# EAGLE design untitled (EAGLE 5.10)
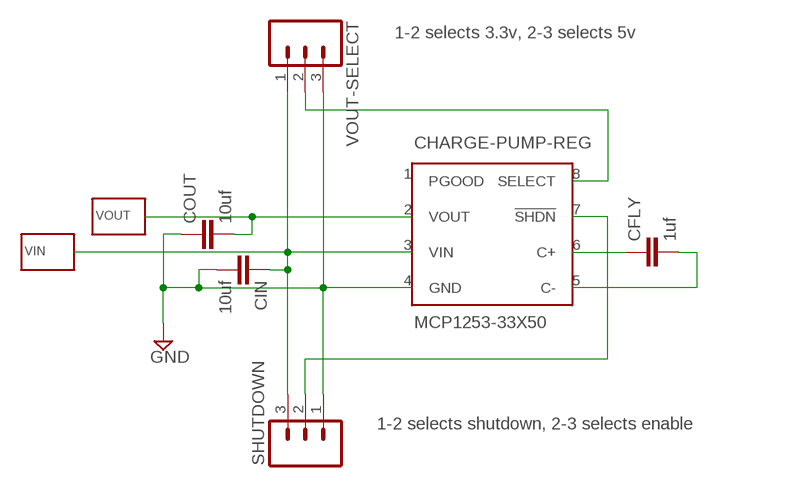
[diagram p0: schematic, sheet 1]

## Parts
CFLY  1uf  C-EUC1206  [C1206]
CHARGE-PUMP-REG  MCP1253-33X50  [8MSOP]
CIN  10uf  C-EUC1206  [C1206]
COUT  10uf  C-EUC1206  [C1206]
SHUTDOWN  M03PTH  [1X03]
VIN  WIREPAD-SMD-NO-VALUE  [WIREPAD-SMD]
VOUT  WIREPAD-SMD-NO-VALUE  [WIREPAD-SMD]
VOUT-SELECT  M03PTH  [1X03]

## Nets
GND: CHARGE-PUMP-REG.4(GND) CIN.2 COUT.1 SHUTDOWN.1 VOUT-SELECT.3
N$2: CHARGE-PUMP-REG.3(VIN) CIN.1 SHUTDOWN.3 VIN.1(P) VOUT-SELECT.1
N$3: CHARGE-PUMP-REG.2(VOUT) COUT.2 VOUT.1(P)
N$4: CHARGE-PUMP-REG.8(SELECT) VOUT-SELECT.2
N$5: CHARGE-PUMP-REG.7(!SHDN) SHUTDOWN.2
N$6: CFLY.1 CHARGE-PUMP-REG.6(C+)
N$7: CFLY.2 CHARGE-PUMP-REG.5(C-)
Unconnected: CHARGE-PUMP-REG.1(PGOOD)

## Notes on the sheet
- 1-2 selects 3.3v, 2-3 selects 5v
- 1-2 selects shutdown, 2-3 selects enable

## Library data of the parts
CFLY CIN COUT = resistor:C-EU: CAPACITOR, European symbol
CHARGE-PUMP-REG = trl:MCP1253-33X50
SHUTDOWN VOUT-SELECT = SparkFun:M03: Header 3 Standard 3-pin 0.1" header. Use with straight break away headers (SKU : PRT-00116), right angle break away headers (PRT-00553), swiss pins (PRT-00743), machine pins (PRT-00117), and female headers (PRT-00115). Molex polarized connector foot print use with SKU : PRT-08232 with associated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
VIN VOUT = trl:WIREPAD-SMD-NO-VALUE

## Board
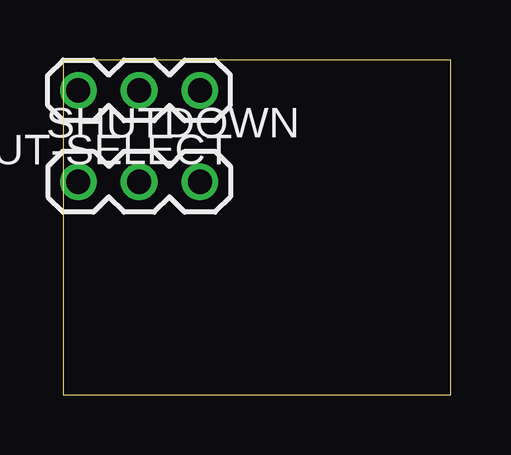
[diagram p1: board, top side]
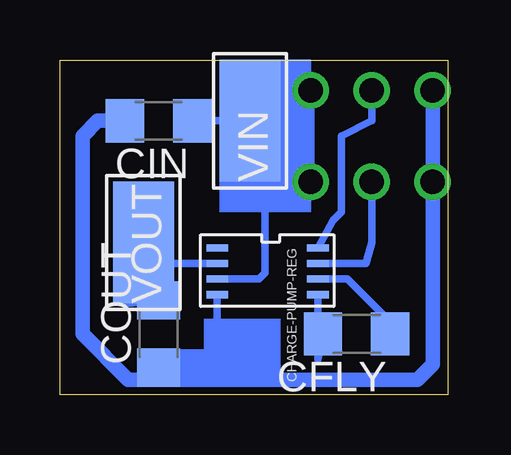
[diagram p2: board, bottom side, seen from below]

Size 16.18 x 13.96 mm. Coordinates in mm from the lower left corner, seen from the top.
Outline: 0,0 16.18,0 16.18,13.96 0,13.96 0,0
Copper layers (1*16): Top 0.035mm / dielectric 1.5mm / Bottom 0.035mm
Design rules "default": minimum track width 10mil, minimum drill 24mil, track to track 8mil, track to pad 8mil, pad to pad 8mil, via to via 8mil, smd to smd 8mil, copper to edge 40mil, drill to drill 8mil, minimum pad ring 10mil, minimum via ring 8mil, stop-mask expansion 4mil, vias tented up to drill 0mil, thermal gap 10mil

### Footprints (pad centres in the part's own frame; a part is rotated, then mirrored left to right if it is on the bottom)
C1206 = smd 1.6 x 1.8: 1 -1.4,0; 2 1.4,0
8MSOP = smd 0.3 x 0.9: 1 -1.05,-2; 2 -0.4,-2; 3 0.25,-2; 4 0.9,-2; 5 0.9,2.2; 6 0.25,2.2; 7 -0.4,2.2; 8 -1.05,2.2
1X03 = drill 1.016 round: 1 0,0; 2 2.54,0; 3 5.08,0
WIREPAD-SMD = smd 2.54 x 5.08: 1 0,0

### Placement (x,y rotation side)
CFLY  3.81,2.54 180 bottom
CHARGE-PUMP-REG  7.62,5.08 270 bottom
CIN  12.06,11.43 180 bottom
COUT  12.06,2.54 90 bottom
SHUTDOWN  0.64,8.89 0 top
VIN  8.26,11.43 0 bottom
VOUT  12.7,6.35 0 bottom
VOUT-SELECT  5.71,12.7 180 top

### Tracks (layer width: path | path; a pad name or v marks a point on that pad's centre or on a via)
GND
  Bottom 0.305: CHARGE-PUMP-REG.4 9.62,0.54 12.06,0.64 11.94,1.27 COUT.1
  Bottom 0.61: CIN.2 14.61,11.43 15.24,10.79 15.24,3.17 15.24,2.54 13.34,0.64 12.06,0.64 | 12.06,0.64 12.2,1.27 COUT.1 | VOUT-SELECT.3 SHUTDOWN.1 0.64,1.27 1.27,0.64 11.43,0.64 12.06,0.64
N$2
  Bottom 0.305: VIN.1 CIN.1 | CHARGE-PUMP-REG.3 7.87,4.83 7.62,5.08 7.62,7.62 7.62,10.16 VIN.1 | SHUTDOWN.3 VOUT-SELECT.1 6.99,12.7 VIN.1
N$3
  Bottom 0.305: CHARGE-PUMP-REG.2 13.34,5.48 | 13.34,5.48 COUT.2 | COUT.2 13.34,3.81 COUT.2 | COUT.2 13.34,5.48 | 13.34,5.48 VOUT.1
N$4
  Bottom 0.305: CHARGE-PUMP-REG.8 4.79,7.28 4.45,7.62 4.45,10.79 3.17,11.43 VOUT-SELECT.2
N$5
  Bottom 0.305: CHARGE-PUMP-REG.7 3.41,5.48 3.17,6.35 SHUTDOWN.2
N$6
  Bottom 0.305: CHARGE-PUMP-REG.6 4.2,4.83 1.91,2.54 CFLY.1
N$7
  Bottom 0.305: CHARGE-PUMP-REG.5 5.42,1.48 CFLY.2
(copper drawn outside any net)
  shapes: Bottom area x3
